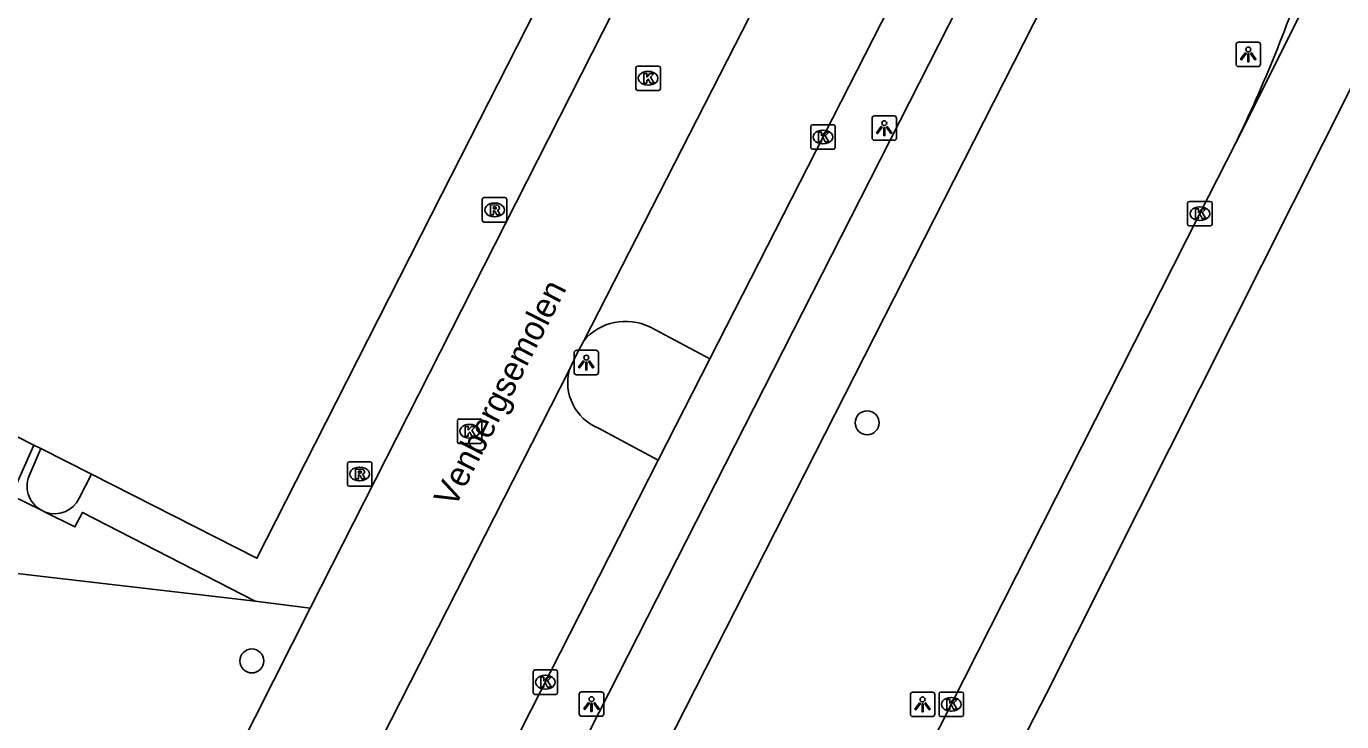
# Model space of a CAD drawing. Extents: x 161243 to 161752, y 384138 to 384885.
# Drawn here: x 161533.2 to 161586.9, y 384440.9 to 384469.3 of the extents above; entities that cross this region are included whole.
import ezdxf

# ---------------------------------------------------------------- set-up
doc = ezdxf.new("R2010")
doc.units = 0
for name, color, linetype in [('IMGEO_Boom', 7, 'Continuous'), ('IMGEO_Fietspad_gesloten', 7, 'Continuous'), ('IMGEO_Kolk', 7, 'Continuous'), ('IMGEO_Lichtpunt', 7, 'Continuous'), ('IMGEO_Openbare_ruimte_label', 7, 'Continuous'), ('IMGEO_Pand', 7, 'Continuous'), ('IMGEO_Parkeervlak_open', 7, 'Continuous'), ('IMGEO_Rijbaan_lokaal_gesloten', 7, 'Continuous'), ('IMGEO_Rijbaan_lokaal_open', 7, 'Continuous'), ('IMGEO_Rioolput', 7, 'Continuous'), ('IMGEO_Voetpad_open', 7, 'Continuous')]:
    doc.layers.add(name, color=color, linetype=linetype)

msp = doc.modelspace()

# ---------------------------------------------------------------- linework, layer by layer
at = {"layer": 'IMGEO_Boom'}
for centre in [(161567.566, 384453.099), (161542.438, 384443.371)]:
    msp.add_circle(centre, 0.489, dxfattribs=at)
at = {"layer": 'IMGEO_Fietspad_gesloten'}
for points in [[(161518.014, 384365.014), (161522.72, 384374.49), (161548.308, 384424.931), (161625.518, 384576.727)], [(161520.707, 384363.649), (161526.535, 384375.146), (161550.415, 384422.299), (161627.114, 384573.143), (161627.772, 384574.506), (161627.927, 384574.874), (161628.195, 384575.423)]]:
    msp.add_lwpolyline(points, dxfattribs=at)
at = {"layer": 'IMGEO_Kolk'}
for p, q in [((161558.123, 384466.744), (161558.123, 384467.596)), ((161558.198, 384467.67), (161559.05, 384467.67)), ((161558.611, 384467.45), (161558.636, 384467.45)), ((161559.124, 384467.596), (161559.124, 384466.744)), ((161558.634, 384466.89), (161558.609, 384466.89)), ((161559.05, 384466.67), (161558.198, 384466.67)), ((161565.337, 384465.27), (161566.189, 384465.27)), ((161565.262, 384464.344), (161565.262, 384465.196)), ((161565.75, 384465.05), (161565.775, 384465.05)), ((161566.263, 384465.196), (161566.263, 384464.344)), ((161566.189, 384464.27), (161565.337, 384464.27)), ((161565.773, 384464.49), (161565.748, 384464.49)), ((161580.657, 384461.215), (161580.657, 384462.067)), ((161580.732, 384462.141), (161581.584, 384462.141)), ((161581.658, 384462.067), (161581.658, 384461.215)), ((161581.145, 384461.921), (161581.17, 384461.921)), ((161581.584, 384461.141), (161580.732, 384461.141)), ((161581.168, 384461.361), (161581.143, 384461.361)), ((161550.832, 384452.327), (161550.832, 384453.179)), ((161550.907, 384453.253), (161551.759, 384453.253)), ((161551.32, 384453.033), (161551.345, 384453.033)), ((161551.833, 384453.179), (161551.833, 384452.327)), ((161551.343, 384452.473), (161551.318, 384452.473)), ((161551.759, 384452.253), (161550.907, 384452.253)), ((161553.926, 384442.079), (161553.926, 384442.931)), ((161554.001, 384443.005), (161554.853, 384443.005)), ((161554.414, 384442.785), (161554.439, 384442.785)), ((161554.927, 384442.931), (161554.927, 384442.079)), ((161554.437, 384442.225), (161554.412, 384442.225)), ((161554.853, 384442.005), (161554.001, 384442.005)), ((161570.505, 384441.172), (161570.505, 384442.024)), ((161570.58, 384442.098), (161571.432, 384442.098)), ((161570.993, 384441.878), (161571.018, 384441.878)), ((161571.506, 384442.024), (161571.506, 384441.172)), ((161571.432, 384441.098), (161570.58, 384441.098)), ((161571.016, 384441.318), (161570.991, 384441.318))]:
    msp.add_line(p, q, dxfattribs=at)
for points in [[(161558.123, 384466.744), (161558.123, 384467.596)], [(161558.198, 384467.67), (161559.05, 384467.67)], [(161559.124, 384467.596), (161559.124, 384466.744)], [(161558.444, 384467.37), (161558.567, 384467.37), (161558.567, 384467.219), (161558.697, 384467.37), (161558.861, 384467.37), (161558.715, 384467.219), (161558.868, 384466.97), (161558.716, 384466.97), (161558.631, 384467.134), (161558.567, 384467.067), (161558.567, 384466.97), (161558.444, 384466.97), (161558.444, 384467.37)], [(161559.05, 384466.67), (161558.198, 384466.67)], [(161565.337, 384465.27), (161566.189, 384465.27)], [(161565.262, 384464.344), (161565.262, 384465.196)], [(161565.583, 384464.97), (161565.706, 384464.97), (161565.706, 384464.819), (161565.836, 384464.97), (161566, 384464.97), (161565.854, 384464.819), (161566.007, 384464.57), (161565.855, 384464.57), (161565.77, 384464.734), (161565.706, 384464.667), (161565.706, 384464.57), (161565.583, 384464.57), (161565.583, 384464.97)], [(161566.263, 384465.196), (161566.263, 384464.344)], [(161566.189, 384464.27), (161565.337, 384464.27)], [(161580.657, 384461.215), (161580.657, 384462.067)], [(161580.732, 384462.141), (161581.584, 384462.141)], [(161581.658, 384462.067), (161581.658, 384461.215)], [(161580.978, 384461.841), (161581.101, 384461.841), (161581.101, 384461.69), (161581.231, 384461.841), (161581.395, 384461.841), (161581.249, 384461.69), (161581.402, 384461.441), (161581.25, 384461.441), (161581.165, 384461.605), (161581.101, 384461.538), (161581.101, 384461.441), (161580.978, 384461.441), (161580.978, 384461.841)], [(161581.584, 384461.141), (161580.732, 384461.141)], [(161550.832, 384452.327), (161550.832, 384453.179)], [(161550.907, 384453.253), (161551.759, 384453.253)], [(161551.153, 384452.953), (161551.276, 384452.953), (161551.276, 384452.802), (161551.406, 384452.953), (161551.57, 384452.953), (161551.424, 384452.802), (161551.577, 384452.553), (161551.425, 384452.553), (161551.34, 384452.717), (161551.276, 384452.65), (161551.276, 384452.553), (161551.153, 384452.553), (161551.153, 384452.953)], [(161551.833, 384453.179), (161551.833, 384452.327)], [(161551.759, 384452.253), (161550.907, 384452.253)], [(161553.926, 384442.079), (161553.926, 384442.931)], [(161554.001, 384443.005), (161554.853, 384443.005)], [(161554.247, 384442.705), (161554.37, 384442.705), (161554.37, 384442.554), (161554.5, 384442.705), (161554.664, 384442.705), (161554.518, 384442.554), (161554.671, 384442.305), (161554.519, 384442.305), (161554.434, 384442.469), (161554.37, 384442.402), (161554.37, 384442.305), (161554.247, 384442.305), (161554.247, 384442.705)], [(161554.927, 384442.931), (161554.927, 384442.079)], [(161554.853, 384442.005), (161554.001, 384442.005)], [(161570.505, 384441.172), (161570.505, 384442.024)], [(161570.58, 384442.098), (161571.432, 384442.098)], [(161570.826, 384441.798), (161570.949, 384441.798), (161570.949, 384441.647), (161571.079, 384441.798), (161571.243, 384441.798), (161571.097, 384441.647), (161571.25, 384441.398), (161571.098, 384441.398), (161571.013, 384441.562), (161570.949, 384441.495), (161570.949, 384441.398), (161570.826, 384441.398), (161570.826, 384441.798)], [(161571.506, 384442.024), (161571.506, 384441.172)], [(161571.432, 384441.098), (161570.58, 384441.098)]]:
    msp.add_lwpolyline(points, dxfattribs=at)
for centre, start, end in [((161558.2, 384467.594), 91.552, 178.448), ((161558.2, 384467.594), 91.552, 178.448), ((161559.048, 384467.594), 1.552, 88.448), ((161559.048, 384467.594), 1.552, 88.448), ((161558.2, 384466.746), 181.552, 268.448), ((161558.2, 384466.746), 181.552, 268.448), ((161559.048, 384466.746), 271.552, 358.448), ((161559.048, 384466.746), 271.552, 358.448), ((161565.339, 384465.194), 91.552, 178.448), ((161565.339, 384465.194), 91.552, 178.448), ((161566.187, 384465.194), 1.552, 88.448), ((161566.187, 384465.194), 1.552, 88.448), ((161565.339, 384464.346), 181.552, 268.448), ((161565.339, 384464.346), 181.552, 268.448), ((161566.187, 384464.346), 271.552, 358.448), ((161566.187, 384464.346), 271.552, 358.448), ((161580.734, 384462.065), 91.552, 178.448), ((161580.734, 384462.065), 91.552, 178.448), ((161581.582, 384462.065), 1.552, 88.448), ((161581.582, 384462.065), 1.552, 88.448), ((161580.734, 384461.217), 181.552, 268.448), ((161580.734, 384461.217), 181.552, 268.448), ((161581.582, 384461.217), 271.552, 358.448), ((161581.582, 384461.217), 271.552, 358.448), ((161550.909, 384453.177), 91.552, 178.448), ((161550.909, 384453.177), 91.552, 178.448), ((161551.757, 384453.177), 1.552, 88.448), ((161551.757, 384453.177), 1.552, 88.448), ((161550.909, 384452.329), 181.552, 268.448), ((161550.909, 384452.329), 181.552, 268.448), ((161551.757, 384452.329), 271.552, 358.448), ((161551.757, 384452.329), 271.552, 358.448), ((161554.003, 384442.929), 91.552, 178.448), ((161554.003, 384442.929), 91.552, 178.448), ((161554.851, 384442.929), 1.552, 88.448), ((161554.851, 384442.929), 1.552, 88.448), ((161554.003, 384442.081), 181.552, 268.448), ((161554.003, 384442.081), 181.552, 268.448), ((161554.851, 384442.081), 271.552, 358.448), ((161554.851, 384442.081), 271.552, 358.448), ((161570.582, 384442.022), 91.552, 178.448), ((161570.582, 384442.022), 91.552, 178.448), ((161571.43, 384442.022), 1.552, 88.448), ((161571.43, 384442.022), 1.552, 88.448), ((161570.582, 384441.174), 181.552, 268.448), ((161570.582, 384441.174), 181.552, 268.448), ((161571.43, 384441.174), 271.552, 358.448), ((161571.43, 384441.174), 271.552, 358.448)]:
    msp.add_arc(centre, 0.0765, start, end, dxfattribs=at)
for centre, major_axis, ratio, start_param, end_param in [((161558.61, 384467.17), (-0.387, 0.002), 0.722429, 4.712389, 7.853982), ((161558.635, 384467.17), (-0.39, 0.002), 0.717154, 1.570796, 4.712389), ((161565.749, 384464.77), (-0.387, 0.002), 0.722429, 4.712389, 7.853982), ((161565.774, 384464.77), (-0.39, 0.002), 0.717154, 1.570796, 4.712389), ((161581.144, 384461.641), (-0.387, 0.002), 0.722429, 4.712389, 7.853982), ((161581.169, 384461.641), (-0.39, 0.002), 0.717154, 1.570796, 4.712389), ((161551.319, 384452.753), (-0.387, 0.002), 0.722429, 4.712389, 7.853982), ((161551.344, 384452.753), (-0.39, 0.002), 0.717154, 1.570796, 4.712389), ((161554.413, 384442.505), (-0.387, 0.002), 0.722429, 4.712389, 7.853982), ((161554.438, 384442.505), (-0.39, 0.002), 0.717154, 1.570796, 4.712389), ((161570.992, 384441.598), (-0.387, 0.002), 0.722429, 4.712389, 7.853982), ((161571.017, 384441.598), (-0.39, 0.002), 0.717154, 1.570796, 4.712389)]:
    msp.add_ellipse(centre, major_axis=major_axis, ratio=ratio, start_param=start_param, end_param=end_param, dxfattribs=at)
at = {"layer": 'IMGEO_Lichtpunt'}
for p, q in [((161582.636, 384468.547), (161582.636, 384467.74)), ((161582.636, 384468.547), (161582.636, 384467.74)), ((161583.538, 384468.642), (161582.73, 384468.642)), ((161583.538, 384468.642), (161582.73, 384468.642)), ((161583.632, 384467.74), (161583.632, 384468.547)), ((161583.632, 384467.74), (161583.632, 384468.547)), ((161582.73, 384467.646), (161583.538, 384467.646)), ((161582.73, 384467.646), (161583.538, 384467.646)), ((161567.768, 384465.536), (161567.768, 384464.729)), ((161567.768, 384465.536), (161567.768, 384464.729)), ((161568.67, 384465.631), (161567.862, 384465.631)), ((161568.67, 384465.631), (161567.862, 384465.631)), ((161568.764, 384464.729), (161568.764, 384465.536)), ((161568.764, 384464.729), (161568.764, 384465.536)), ((161567.862, 384464.635), (161568.67, 384464.635)), ((161567.862, 384464.635), (161568.67, 384464.635)), ((161555.599, 384455.963), (161555.599, 384455.156)), ((161555.599, 384455.963), (161555.599, 384455.156)), ((161556.501, 384456.058), (161555.693, 384456.058)), ((161556.501, 384456.058), (161555.693, 384456.058)), ((161556.595, 384455.156), (161556.595, 384455.963)), ((161556.595, 384455.156), (161556.595, 384455.963)), ((161555.693, 384455.062), (161556.501, 384455.062)), ((161555.693, 384455.062), (161556.501, 384455.062)), ((161555.813, 384442.015), (161555.813, 384441.208)), ((161555.813, 384442.015), (161555.813, 384441.208)), ((161556.715, 384442.11), (161555.907, 384442.11)), ((161556.715, 384442.11), (161555.907, 384442.11)), ((161556.809, 384441.208), (161556.809, 384442.015)), ((161556.809, 384441.208), (161556.809, 384442.015)), ((161569.333, 384442.002), (161569.333, 384441.195)), ((161569.333, 384442.002), (161569.333, 384441.195)), ((161570.235, 384442.097), (161569.427, 384442.097)), ((161570.235, 384442.097), (161569.427, 384442.097)), ((161570.329, 384441.195), (161570.329, 384442.002)), ((161570.329, 384441.195), (161570.329, 384442.002)), ((161555.907, 384441.114), (161556.715, 384441.114)), ((161555.907, 384441.114), (161556.715, 384441.114)), ((161569.427, 384441.101), (161570.235, 384441.101)), ((161569.427, 384441.101), (161570.235, 384441.101))]:
    msp.add_line(p, q, dxfattribs=at)
for points in [[(161583.01, 384468.211), (161583.049, 384468.183), (161582.861, 384467.921), (161582.823, 384467.948), (161583.01, 384468.211)], [(161583.112, 384468.163), (161583.159, 384468.163), (161583.159, 384467.841), (161583.112, 384467.841), (161583.112, 384468.163)], [(161583.222, 384468.183), (161583.26, 384468.21), (161583.447, 384467.948), (161583.408, 384467.92), (161583.222, 384468.183)], [(161568.142, 384465.2), (161568.181, 384465.172), (161567.993, 384464.91), (161567.955, 384464.937), (161568.142, 384465.2)], [(161568.244, 384465.152), (161568.291, 384465.152), (161568.291, 384464.83), (161568.244, 384464.83), (161568.244, 384465.152)], [(161568.354, 384465.172), (161568.392, 384465.199), (161568.579, 384464.937), (161568.54, 384464.909), (161568.354, 384465.172)], [(161555.973, 384455.627), (161556.012, 384455.599), (161555.824, 384455.337), (161555.786, 384455.364), (161555.973, 384455.627)], [(161556.185, 384455.599), (161556.223, 384455.626), (161556.41, 384455.364), (161556.371, 384455.336), (161556.185, 384455.599)], [(161556.075, 384455.579), (161556.122, 384455.579), (161556.122, 384455.257), (161556.075, 384455.257), (161556.075, 384455.579)], [(161556.187, 384441.679), (161556.226, 384441.651), (161556.038, 384441.389), (161556, 384441.416), (161556.187, 384441.679)], [(161556.289, 384441.631), (161556.336, 384441.631), (161556.336, 384441.309), (161556.289, 384441.309), (161556.289, 384441.631)], [(161556.399, 384441.651), (161556.437, 384441.678), (161556.624, 384441.416), (161556.585, 384441.388), (161556.399, 384441.651)], [(161569.707, 384441.666), (161569.746, 384441.638), (161569.558, 384441.376), (161569.52, 384441.403), (161569.707, 384441.666)], [(161569.919, 384441.638), (161569.957, 384441.665), (161570.144, 384441.403), (161570.105, 384441.375), (161569.919, 384441.638)], [(161569.809, 384441.618), (161569.856, 384441.618), (161569.856, 384441.296), (161569.809, 384441.296), (161569.809, 384441.618)]]:
    msp.add_lwpolyline(points, dxfattribs=at)
for centre in [(161583.135, 384468.345), (161568.267, 384465.334), (161556.098, 384455.761), (161556.312, 384441.813), (161569.832, 384441.8)]:
    msp.add_circle(centre, 0.0994, dxfattribs=at)
for centre, start, end in [((161582.73, 384468.547), 90, 180), ((161582.73, 384468.547), 90, 180), ((161583.538, 384468.547), 0, 90), ((161583.538, 384468.547), 0, 90), ((161582.73, 384467.74), 180, 270), ((161582.73, 384467.74), 180, 270), ((161583.538, 384467.74), 270, 0), ((161583.538, 384467.74), 270, 360), ((161567.862, 384465.536), 90, 180), ((161567.862, 384465.536), 90, 180), ((161568.67, 384465.536), 0, 90), ((161568.67, 384465.536), 0, 90), ((161567.862, 384464.729), 180, 270), ((161567.862, 384464.729), 180, 270), ((161568.67, 384464.729), 270, 0), ((161568.67, 384464.729), 270, 360), ((161555.693, 384455.963), 90, 180), ((161555.693, 384455.963), 90, 180), ((161556.501, 384455.963), 0, 90), ((161556.501, 384455.963), 0, 90), ((161555.693, 384455.156), 180, 270), ((161555.693, 384455.156), 180, 270), ((161556.501, 384455.156), 270, 0), ((161556.501, 384455.156), 270, 360), ((161555.907, 384442.015), 90, 180), ((161555.907, 384442.015), 90, 180), ((161556.715, 384442.015), 0, 90), ((161556.715, 384442.015), 0, 90), ((161569.427, 384442.002), 90, 180), ((161569.427, 384442.002), 90, 180), ((161570.235, 384442.002), 0, 90), ((161570.235, 384442.002), 0, 90), ((161555.907, 384441.208), 180, 270), ((161555.907, 384441.208), 180, 270), ((161556.715, 384441.208), 270, 0), ((161556.715, 384441.208), 270, 360), ((161569.427, 384441.195), 180, 270), ((161569.427, 384441.195), 180, 270), ((161570.235, 384441.195), 270, 0), ((161570.235, 384441.195), 270, 360)]:
    msp.add_arc(centre, 0.0946, start, end, dxfattribs=at)
at = {"layer": 'IMGEO_Pand'}
for points in [[(161533.54, 384452.19), (161525.753, 384456.145), (161528.137, 384460.824), (161533.323, 384471), (161537.947, 384480.074), (161543.125, 384490.234), (161545.574, 384495.041), (161546.917, 384494.362), (161549.173, 384498.829), (161547.837, 384499.52), (161548.081, 384500), (161550.264, 384504.297), (161555.424, 384514.452), (161560.039, 384523.536), (161565.227, 384533.748), (161567.615, 384538.447), (161568.979, 384537.766), (161570.138, 384540.132)], [(161535.884, 384451), (161542.645, 384447.566), (161545.025, 384452.253), (161550.195, 384462.432), (161554.798, 384471.495), (161559.976, 384481.689), (161562.212, 384486.092), (161564.22, 384485.074), (161565.568, 384487.732), (161562.083, 384489.499), (161560.841, 384490.129), (161561.999, 384492.413), (161563.241, 384491.783), (161564.728, 384491.029), (161564.842, 384491.252), (161567.082, 384495.672), (161569.275, 384500), (161572.257, 384505.884), (161576.837, 384514.921), (161582.032, 384525.172), (161584.435, 384529.913), (161583.106, 384530.578), (161585.626, 384535.56)], [(161533.54, 384452.19), (161533.827, 384452.044)], [(161533.827, 384452.044), (161535.884, 384451)]]:
    msp.add_lwpolyline(points, dxfattribs=at)
at = {"layer": 'IMGEO_Parkeervlak_open'}
for points in [[(161561.138, 384455.713), (161558.693, 384457.011)], [(161559.035, 384451.577), (161556.59, 384452.875)]]:
    msp.add_lwpolyline(points, dxfattribs=at)
for centre, radius, start, end in [((161557.702, 384455.009), 2.234, 63.6544, 139.8704), ((161557.368, 384454.75), 2.029, 164.9343, 247.4683)]:
    msp.add_arc(centre, radius, start, end, dxfattribs=at)
at = {"layer": 'IMGEO_Rijbaan_lokaal_gesloten'}
for points in [[(161638.668, 384567.921), (161627.681, 384546.777), (161605.302, 384502.824), (161593.763, 384479.586), (161574.873, 384442.021), (161545.035, 384383.956), (161539.238, 384372.041), (161525.285, 384343.063), (161517.236, 384325.784), (161510.904, 384308.827), (161504.035, 384290.582), (161498.991, 384275.235), (161492.66, 384254.201), (161489.655, 384243.039), (161484.933, 384223.293), (161481.713, 384206.981), (161478.494, 384189.488), (161475.768, 384168.523)], [(161626.74, 384552.582), (161582.611, 384464.512)], [(161582.611, 384464.512), (161581.158, 384461.641), (161571.006, 384441.598), (161562.641, 384425.122), (161560.182, 384420.321), (161554.738, 384409.551), (161544.577, 384389.539), (161535.296, 384371.307)]]:
    msp.add_lwpolyline(points, dxfattribs=at)
msp.add_arc((161531.691, 384489.388), 56.672, 333.9628, 342.0789, dxfattribs=at)
at = {"layer": 'IMGEO_Rijbaan_lokaal_open'}
for points in [[(161544.826, 384445.532), (161561.636, 384478.649)], [(161566.167, 384476.349), (161555.994, 384456.449)], [(161555.994, 384456.449), (161555.669, 384455.831), (161555.408, 384455.277)], [(161555.408, 384455.277), (161544.686, 384434.205)], [(161539.566, 384435.11), (161544.826, 384445.532)]]:
    msp.add_lwpolyline(points, dxfattribs=at)
at = {"layer": 'IMGEO_Rioolput'}
for p, q in [((161551.851, 384461.368), (161551.851, 384462.22)), ((161551.926, 384462.294), (161552.778, 384462.294)), ((161552.339, 384462.074), (161552.364, 384462.074)), ((161552.852, 384462.22), (161552.852, 384461.368)), ((161552.362, 384461.514), (161552.337, 384461.514)), ((161552.778, 384461.294), (161551.926, 384461.294)), ((161546.34, 384450.58), (161546.34, 384451.432)), ((161546.415, 384451.506), (161547.267, 384451.506)), ((161547.341, 384451.432), (161547.341, 384450.58)), ((161546.828, 384451.286), (161546.853, 384451.286)), ((161547.267, 384450.506), (161546.415, 384450.506)), ((161546.851, 384450.726), (161546.826, 384450.726))]:
    msp.add_line(p, q, dxfattribs=at)
for points in [[(161551.851, 384461.368), (161551.851, 384462.22)], [(161551.926, 384462.294), (161552.778, 384462.294)], [(161552.852, 384462.22), (161552.852, 384461.368)], [(161552.44, 384461.992), (161552.188, 384461.994), (161552.188, 384461.594)], [(161552.188, 384461.594), (161552.312, 384461.594), (161552.312, 384461.756), (161552.323, 384461.756)], [(161552.366, 384461.913), (161552.312, 384461.913), (161552.312, 384461.832)], [(161552.312, 384461.832), (161552.364, 384461.832)], [(161552.37, 384461.727), (161552.441, 384461.594), (161552.581, 384461.594), (161552.516, 384461.72)], [(161552.778, 384461.294), (161551.926, 384461.294)], [(161546.34, 384450.58), (161546.34, 384451.432)], [(161546.415, 384451.506), (161547.267, 384451.506)], [(161547.341, 384451.432), (161547.341, 384450.58)], [(161546.929, 384451.204), (161546.677, 384451.206), (161546.677, 384450.806)], [(161546.677, 384450.806), (161546.801, 384450.806), (161546.801, 384450.968), (161546.812, 384450.968)], [(161546.855, 384451.125), (161546.801, 384451.125), (161546.801, 384451.044)], [(161546.801, 384451.044), (161546.853, 384451.044)], [(161546.859, 384450.939), (161546.93, 384450.806), (161547.07, 384450.806), (161547.005, 384450.932)], [(161547.267, 384450.506), (161546.415, 384450.506)]]:
    msp.add_lwpolyline(points, dxfattribs=at)
for centre, radius, start, end in [((161551.928, 384462.218), 0.0765, 91.552, 178.448), ((161551.928, 384462.218), 0.0765, 91.552, 178.448), ((161552.776, 384462.218), 0.0765, 1.552, 88.448), ((161552.776, 384462.218), 0.0765, 1.552, 88.448), ((161552.322, 384461.703), 0.0533, 26.0293, 88.6989), ((161552.348, 384462.021), 0.19, 274.7715, 282.9687), ((161552.372, 384461.817), 0.0964, 77.0061, 93.1865), ((161552.386, 384461.874), 0.0378, 276.6634, 79.6772), ((161552.439, 384461.882), 0.109, 350.3612, 89.416), ((161552.437, 384461.882), 0.112, 277.5842, 350.9817), ((161552.421, 384461.667), 0.108, 29.5134, 73.7905), ((161551.928, 384461.37), 0.0765, 181.552, 268.448), ((161551.928, 384461.37), 0.0765, 181.552, 268.448), ((161552.776, 384461.37), 0.0765, 271.552, 358.448), ((161552.776, 384461.37), 0.0765, 271.552, 358.448), ((161546.417, 384451.43), 0.0765, 91.552, 178.448), ((161546.417, 384451.43), 0.0765, 91.552, 178.448), ((161547.265, 384451.43), 0.0765, 1.552, 88.448), ((161547.265, 384451.43), 0.0765, 1.552, 88.448), ((161546.811, 384450.915), 0.0533, 26.0293, 88.6989), ((161546.837, 384451.233), 0.19, 274.7715, 282.9687), ((161546.861, 384451.029), 0.0964, 77.0061, 93.1865), ((161546.875, 384451.086), 0.0378, 276.6634, 79.6772), ((161546.928, 384451.094), 0.109, 350.3612, 89.416), ((161546.926, 384451.094), 0.112, 277.5842, 350.9817), ((161546.91, 384450.879), 0.108, 29.5134, 73.7905), ((161546.417, 384450.582), 0.0765, 181.552, 268.448), ((161546.417, 384450.582), 0.0765, 181.552, 268.448), ((161547.265, 384450.582), 0.0765, 271.552, 358.448), ((161547.265, 384450.582), 0.0765, 271.552, 358.448)]:
    msp.add_arc(centre, radius, start, end, dxfattribs=at)
for centre, major_axis, ratio, start_param, end_param in [((161552.338, 384461.794), (-0.387, 0.002), 0.722429, 4.712389, 7.853982), ((161552.363, 384461.794), (-0.39, 0.002), 0.717154, 1.570796, 4.712389), ((161546.827, 384451.006), (-0.387, 0.002), 0.722429, 4.712389, 7.853982), ((161546.852, 384451.006), (-0.39, 0.002), 0.717154, 1.570796, 4.712389)]:
    msp.add_ellipse(centre, major_axis=major_axis, ratio=ratio, start_param=start_param, end_param=end_param, dxfattribs=at)
at = {"layer": 'IMGEO_Voetpad_open'}
for points in [[(161570.493, 384474.049), (161561.138, 384455.713)], [(161561.138, 384455.713), (161559.035, 384451.577)], [(161533.842, 384449.528), (161532.616, 384450.135), (161533.54, 384452.19)], [(161533.827, 384452.044), (161533.389, 384451.032)], [(161559.035, 384451.577), (161549.816, 384433.449)], [(161535.884, 384451), (161535.389, 384450.014)], [(161533.998, 384449.45), (161533.842, 384449.528)], [(161542.574, 384445.815), (161535.519, 384449.439), (161535.215, 384448.848), (161533.998, 384449.45)], [(161524.754, 384447.882), (161542.574, 384445.815)], [(161544.826, 384445.532), (161542.574, 384445.815)]]:
    msp.add_lwpolyline(points, dxfattribs=at)
for centre, start, end in [((161534.375, 384450.509), 152.029, 241.4953), ((161534.383, 384450.497), 249.809, 334.3325)]:
    msp.add_arc(centre, 1.116, start, end, dxfattribs=at)

# ---------------------------------------------------------------- texts
at = {"layer": 'IMGEO_Openbare_ruimte_label'}
msp.add_text('Venbergsemolen', height=1, rotation=62.9993, dxfattribs=at).set_placement((161550.721, 384449.588))

doc.saveas('drawing.dxf')
